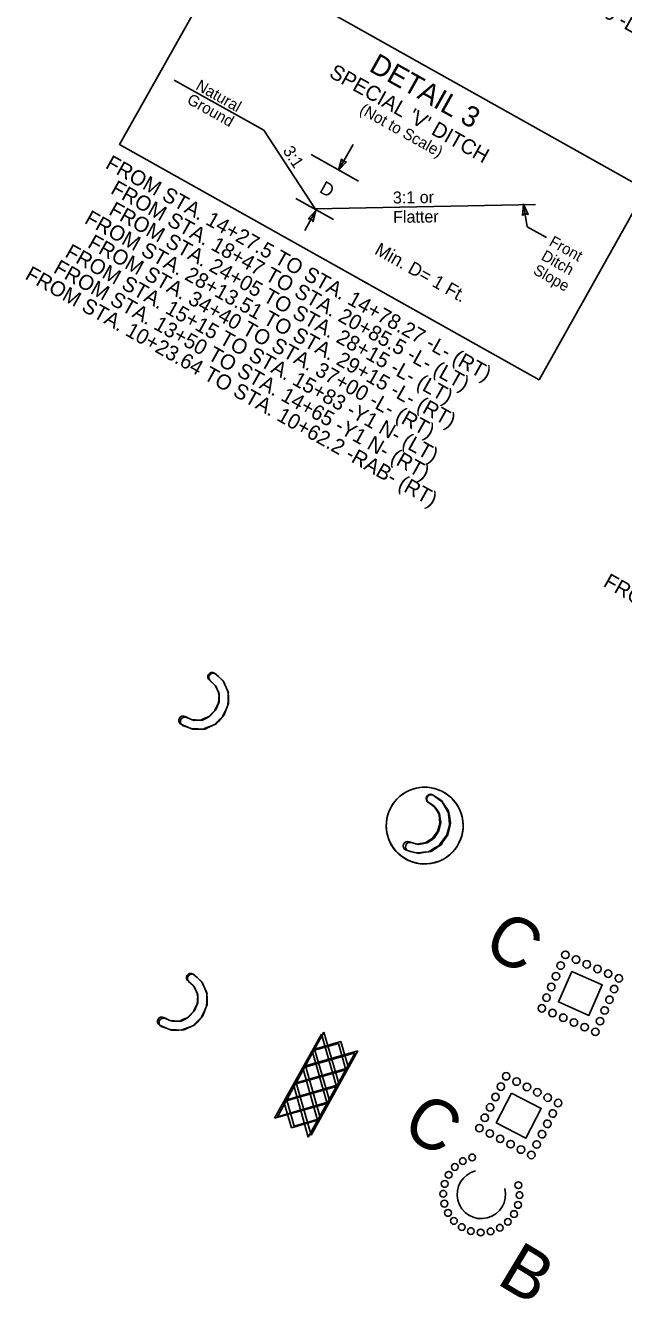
# Model space of a CAD drawing. Extents: x 2283629 to 2286552, y 529718 to 531440.
# Drawn here: x 2284114 to 2284293.2, y 530694.7 to 531076.3 of the extents above; entities that cross this region are included whole.
import ezdxf

# ---------------------------------------------------------------- set-up
doc = ezdxf.new("R2010")
doc.units = 0
for name, color, linetype in [('Draft_Corridor_Graphics_Final', 7, 'Continuous'), ('Draft_RDY_Construction_Class_Element', 7, 'Continuous'), ('P_NCDOT_Terrain_Breakline', 7, 'Continuous'), ('P_NCDOT_Terrain_Hole', 7, 'Continuous'), ('P_NCDOT_Terrain_Island', 7, 'Continuous'), ('P_NCDOT_Terrain_Model_Contour_Major', 7, 'Continuous'), ('P_NCDOT_Terrain_Model_Contour_Minor', 7, 'Continuous'), ('P_NCDOT_Terrain_Model_Triangles', 7, 'Continuous'), ('P_NCDOT_Terrain_Void', 7, 'Continuous'), ('P_RDY_TC_Pvmt_Asphalt_Intermediate_Course', 7, 'Continuous'), ('P_RDY_TC_Pvmt_Asphalt_Surface_Course', 7, 'Continuous'), ('P_RDY_TL_Sidewalk', 7, 'Continuous'), ('P_RDY_XS_Guardrail_Warrant_Red_Flag', 7, 'Continuous')]:
    doc.layers.add(name, color=color, linetype=linetype)

msp = doc.modelspace()

# ---------------------------------------------------------------- linework, layer by layer
at = {"layer": 'Draft_Corridor_Graphics_Final'}
for p, q in [((2284170.65, 530878.85), (2284170.9, 530878.63)), ((2284169.3, 530869.39), (2284168.24, 530868.85)), ((2284171.05, 530871.36), (2284171.05, 530871.35)), ((2284167.24, 530868.36), (2284167.03, 530868.25)), ((2284164.27, 530788.68), (2284164.51, 530788.46)), ((2284164.66, 530781.19), (2284164.66, 530781.18)), ((2284160.85, 530778.19), (2284160.64, 530778.08)), ((2284162.91, 530779.22), (2284161.85, 530778.68))]:
    msp.add_line(p, q, dxfattribs=at)
for points in [[(2284161.08, 530866.65), (2284162.53, 530866.11), (2284164.18, 530865.49), (2284164.99, 530865.51), (2284166.33, 530865.54), (2284167.84, 530865.57), (2284167.85, 530865.57), (2284168.18, 530865.73), (2284168.34, 530865.8), (2284169, 530866.1), (2284169.87, 530866.51), (2284170.08, 530866.61), (2284171.11, 530867.09), (2284171.8, 530867.85), (2284173.58, 530869.8), (2284173.59, 530869.81), (2284174.49, 530872.19), (2284174.86, 530873.17), (2284174.82, 530874.63), (2284174.8, 530875.3), (2284174.77, 530876.25), (2284174.77, 530876.33), (2284174.76, 530876.77), (2284174.76, 530876.81), (2284173.97, 530878.42), (2284173.53, 530879.33), (2284173.17, 530880.09), (2284171.81, 530881.29), (2284170.64, 530882.32)], [(2284169.28, 530880.11), (2284170.65, 530878.85), (2284170.9, 530878.63), (2284171.54, 530877.3), (2284171.99, 530876.37), (2284172, 530874.92), (2284172, 530873.72), (2284171.05, 530871.36), (2284171.05, 530871.35), (2284169.3, 530869.39), (2284168.24, 530868.85), (2284167.24, 530868.36), (2284167.03, 530868.25), (2284165.58, 530868.2), (2284164.48, 530868.16), (2284163.74, 530868.45), (2284162.3, 530869.02), (2284162.29, 530869.02)], [(2284154.69, 530776.48), (2284156.14, 530775.94), (2284157.79, 530775.32), (2284158.6, 530775.34), (2284159.94, 530775.37), (2284161.45, 530775.4), (2284161.46, 530775.4), (2284161.79, 530775.56), (2284161.95, 530775.63), (2284162.61, 530775.94), (2284163.48, 530776.34), (2284163.7, 530776.44), (2284164.72, 530776.92), (2284165.42, 530777.68), (2284167.19, 530779.63), (2284167.2, 530779.64), (2284168.1, 530782.02), (2284168.47, 530783), (2284168.43, 530784.46), (2284168.41, 530785.13), (2284168.39, 530786.08), (2284168.38, 530786.16), (2284168.37, 530786.6), (2284168.37, 530786.64), (2284167.58, 530788.25), (2284167.14, 530789.16), (2284166.78, 530789.92), (2284165.42, 530791.12), (2284164.25, 530792.15)], [(2284162.89, 530789.94), (2284164.27, 530788.68), (2284164.51, 530788.46), (2284165.15, 530787.13), (2284165.6, 530786.2), (2284165.61, 530784.75), (2284165.61, 530783.55), (2284164.66, 530781.19), (2284164.66, 530781.18), (2284162.91, 530779.22), (2284161.85, 530778.68), (2284160.85, 530778.19), (2284160.64, 530778.08), (2284159.19, 530778.03), (2284158.09, 530778), (2284157.35, 530778.28), (2284155.91, 530778.85), (2284155.9, 530778.85)]]:
    msp.add_lwpolyline(points, dxfattribs=at)
for centre, radius, start in [((2284169.96, 530881.21), 1.3, 58.4647), ((2284161.78, 530867.79), 1.33, 67.3521), ((2284163.57, 530791.04), 1.3, 58.4647), ((2284155.39, 530777.62), 1.33, 67.3521)]:
    msp.add_arc(centre, radius, start, 238.4647, dxfattribs=at)
at = {"layer": 'P_NCDOT_Terrain_Breakline'}
for p, q in [((2284207.84, 531033.02), (2284212.15, 531040.69)), ((2284199.58, 531037.65), (2284213.8, 531029.67)), ((2284195.01, 531024.54), (2284206.33, 531018.19)), ((2284263.18, 531022.84), (2284264.35, 531016.05)), ((2284201.05, 531020.91), (2284197.71, 531014.96)), ((2284270.15, 531012.79), (2284264.35, 531016.05))]:
    msp.add_line(p, q, dxfattribs=at)
for points in [[(2284174.2, 531097.74), (2284299.87, 531027.2), (2284267.86, 530970.18), (2284142.19, 531040.72), (2284174.2, 531097.74)], [(2284158.54, 531059.99), (2284185.38, 531045.02), (2284200.78, 531021.41), (2284266.77, 531022.73)]]:
    msp.add_lwpolyline(points, dxfattribs=at)
for points in [[(2284210.18, 531035.5), (2284207.84, 531033.02), (2284208.74, 531036.33), (2284209.27, 531035.55)], [(2284262.93, 531019.44), (2284263.18, 531022.84), (2284264.58, 531019.7), (2284263.67, 531019.98)], [(2284198.71, 531018.42), (2284201.05, 531020.91), (2284200.16, 531017.59), (2284199.63, 531018.38)]]:
    msp.add_lwpolyline(points, close=True, dxfattribs=at)
at = {"layer": 'P_NCDOT_Terrain_Model_Contour_Major'}
for p, q in [((2284236.42, 530842.46), (2284234.88, 530843.51)), ((2284236.41, 530842.45), (2284234.88, 530843.5)), ((2284236.41, 530842.45), (2284236.69, 530842.27)), ((2284236.42, 530842.46), (2284236.69, 530842.28)), ((2284237.52, 530841.05), (2284236.69, 530842.28)), ((2284237.51, 530841.04), (2284236.69, 530842.27)), ((2284238.08, 530840.18), (2284237.51, 530841.04)), ((2284238.09, 530840.19), (2284237.52, 530841.05)), ((2284238.29, 530838.75), (2284238.08, 530840.18)), ((2284238.3, 530838.76), (2284238.09, 530840.19)), ((2284238.47, 530837.56), (2284238.29, 530838.75)), ((2284238.47, 530837.57), (2284238.3, 530838.76)), ((2284236.4, 530832.89), (2284237.86, 530835.08)), ((2284236.41, 530832.9), (2284237.86, 530835.09)), ((2284237.86, 530835.1), (2284238.47, 530837.57)), ((2284237.86, 530835.09), (2284238.47, 530837.56)), ((2284237.86, 530835.1), (2284237.86, 530835.09)), ((2284237.86, 530835.09), (2284237.86, 530835.08)), ((2284229.52, 530831.55), (2284231.03, 530831.19)), ((2284229.52, 530831.54), (2284231.03, 530831.18)), ((2284231.03, 530831.19), (2284231.8, 530831.01)), ((2284231.03, 530831.18), (2284231.8, 530831)), ((2284231.8, 530831.01), (2284232.89, 530831.21)), ((2284231.8, 530831), (2284232.88, 530831.2)), ((2284232.88, 530831.2), (2284234.31, 530831.45)), ((2284232.89, 530831.21), (2284234.32, 530831.46)), ((2284234.51, 530831.58), (2284234.31, 530831.45)), ((2284234.51, 530831.59), (2284234.32, 530831.46)), ((2284234.51, 530831.59), (2284235.43, 530832.22)), ((2284234.51, 530831.58), (2284235.42, 530832.21)), ((2284236.4, 530832.89), (2284235.42, 530832.21)), ((2284236.41, 530832.9), (2284235.43, 530832.22))]:
    msp.add_line(p, q, dxfattribs=at)
for points in [[(2284235.91, 530845.89), (2284237.22, 530845.04), (2284238.73, 530844.04), (2284239.2, 530843.34), (2284239.76, 530842.5), (2284240.77, 530841.02), (2284240.77, 530840.98), (2284240.85, 530840.54), (2284240.86, 530840.47), (2284241.02, 530839.52), (2284241.13, 530838.87), (2284241.38, 530837.42), (2284241.15, 530836.41), (2284240.59, 530833.92), (2284240.59, 530833.91), (2284239.1, 530831.73), (2284238.52, 530830.88), (2284237.57, 530830.26), (2284237.37, 530830.13), (2284236.57, 530829.61), (2284235.95, 530829.21), (2284235.81, 530829.12), (2284235.5, 530828.92), (2284235.49, 530828.92), (2284234, 530828.67), (2284232.68, 530828.45), (2284231.88, 530828.32), (2284230.16, 530828.7), (2284228.65, 530829.04)], [(2284235.91, 530845.88), (2284237.21, 530845.03), (2284238.73, 530844.03), (2284239.2, 530843.33), (2284239.76, 530842.49), (2284240.76, 530841.01), (2284240.77, 530840.97), (2284240.84, 530840.53), (2284240.86, 530840.46), (2284241.02, 530839.51), (2284241.13, 530838.86), (2284241.38, 530837.41), (2284241.15, 530836.4), (2284240.59, 530833.91), (2284240.58, 530833.9), (2284239.1, 530831.72), (2284238.52, 530830.87), (2284237.57, 530830.25), (2284237.37, 530830.12), (2284236.56, 530829.6), (2284235.95, 530829.2), (2284235.8, 530829.11), (2284235.5, 530828.91), (2284235.49, 530828.91), (2284234, 530828.66), (2284232.67, 530828.44), (2284231.87, 530828.31), (2284230.16, 530828.69), (2284228.65, 530829.03)]]:
    msp.add_lwpolyline(points, dxfattribs=at)
for centre, radius, start, end in [((2284233.6, 530836.63), 11.5, 66.5279, 238.9333), ((2284233.64, 530836.61), 11.5, 246.5279, 59.1744), ((2284235.39, 530844.69), 1.3, 66.5279, 246.5279), ((2284235.4, 530844.7), 1.3, 66.5279, 246.5279), ((2284233.6, 530836.63), 11.5, 58.9333, 66.5279), ((2284229.18, 530830.25), 1.33, 75.4153, 246.5279), ((2284229.18, 530830.26), 1.33, 75.4153, 246.5279), ((2284233.64, 530836.61), 11.5, 238.6921, 246.5279)]:
    msp.add_arc(centre, radius, start, end, dxfattribs=at)
at = {"layer": 'P_NCDOT_Terrain_Model_Contour_Minor'}
for p, q in [((2284236.43, 530842.29), (2284234.95, 530843.43)), ((2284236.43, 530842.29), (2284234.95, 530843.43)), ((2284236.43, 530842.29), (2284236.69, 530842.09)), ((2284236.43, 530842.29), (2284236.69, 530842.09)), ((2284237.44, 530840.82), (2284236.69, 530842.09)), ((2284237.44, 530840.82), (2284236.69, 530842.09)), ((2284237.96, 530839.93), (2284237.44, 530840.82)), ((2284237.96, 530839.93), (2284237.44, 530840.82)), ((2284238.09, 530838.49), (2284237.96, 530839.93)), ((2284238.09, 530838.49), (2284237.96, 530839.93)), ((2284238.2, 530837.29), (2284238.09, 530838.49)), ((2284238.2, 530837.29), (2284238.09, 530838.49)), ((2284235.87, 530832.75), (2284237.45, 530834.85)), ((2284235.87, 530832.75), (2284237.45, 530834.85)), ((2284237.45, 530834.86), (2284238.2, 530837.29)), ((2284237.45, 530834.86), (2284238.2, 530837.29)), ((2284237.45, 530834.86), (2284237.45, 530834.85)), ((2284237.45, 530834.86), (2284237.45, 530834.85)), ((2284228.92, 530831.79), (2284230.41, 530831.35)), ((2284228.92, 530831.79), (2284230.41, 530831.35)), ((2284230.41, 530831.35), (2284231.17, 530831.12)), ((2284230.41, 530831.35), (2284231.17, 530831.12)), ((2284231.17, 530831.12), (2284232.26, 530831.25)), ((2284231.17, 530831.12), (2284232.26, 530831.25)), ((2284232.26, 530831.25), (2284233.7, 530831.43)), ((2284232.26, 530831.25), (2284233.7, 530831.43)), ((2284233.91, 530831.55), (2284233.7, 530831.43)), ((2284233.91, 530831.55), (2284233.7, 530831.43)), ((2284233.91, 530831.55), (2284234.85, 530832.12)), ((2284233.91, 530831.55), (2284234.85, 530832.12)), ((2284235.87, 530832.75), (2284234.85, 530832.12)), ((2284235.87, 530832.75), (2284234.85, 530832.12))]:
    msp.add_line(p, q, dxfattribs=at)
msp.add_lwpolyline([(2284236.12, 530845.75), (2284237.37, 530844.82), (2284238.83, 530843.73), (2284239.25, 530843.01), (2284239.77, 530842.14), (2284240.69, 530840.6), (2284240.69, 530840.56), (2284240.74, 530840.12), (2284240.75, 530840.05), (2284240.86, 530839.1), (2284240.93, 530838.44), (2284241.09, 530836.98), (2284240.81, 530835.98), (2284240.11, 530833.53), (2284240.1, 530833.52), (2284238.49, 530831.42), (2284237.87, 530830.61), (2284236.88, 530830.05), (2284236.68, 530829.93), (2284235.84, 530829.45), (2284235.21, 530829.09), (2284235.06, 530829.01), (2284234.74, 530828.82), (2284234.73, 530828.82), (2284233.23, 530828.66), (2284231.9, 530828.52), (2284231.09, 530828.43), (2284229.4, 530828.91), (2284227.91, 530829.33)], dxfattribs=at)
msp.add_lwpolyline([(2284236.12, 530845.75), (2284237.37, 530844.82), (2284238.83, 530843.73), (2284239.25, 530843.01), (2284239.77, 530842.14), (2284240.69, 530840.6), (2284240.69, 530840.56), (2284240.74, 530840.12), (2284240.75, 530840.05), (2284240.86, 530839.1), (2284240.93, 530838.44), (2284241.09, 530836.98), (2284240.81, 530835.98), (2284240.11, 530833.53), (2284240.1, 530833.52), (2284238.49, 530831.42), (2284237.87, 530830.61), (2284236.88, 530830.05), (2284236.68, 530829.93), (2284235.84, 530829.45), (2284235.21, 530829.09), (2284235.06, 530829.01), (2284234.74, 530828.82), (2284234.73, 530828.82), (2284233.23, 530828.66), (2284231.9, 530828.52), (2284231.09, 530828.43), (2284229.4, 530828.91), (2284227.91, 530829.33)], dxfattribs=at)
for centre, radius, start, end in [((2284233.62, 530836.65), 11.5, 63.2706, 153.2706), ((2284235.53, 530844.59), 1.3, 63.2706, 243.2706), ((2284235.53, 530844.59), 1.3, 63.2706, 243.2706), ((2284233.62, 530836.65), 11.5, 333.2706, 63.2706), ((2284233.62, 530836.65), 11.5, 153.2706, 243.2706), ((2284228.51, 530830.52), 1.33, 72.158, 243.2706), ((2284228.51, 530830.52), 1.33, 72.158, 243.2706), ((2284233.62, 530836.65), 11.5, 243.2706, 333.2706)]:
    msp.add_arc(centre, radius, start, end, dxfattribs=at)
at = {"layer": 'P_NCDOT_Terrain_Model_Triangles'}
for p, q in [((2284170.83, 530878.62), (2284171.06, 530878.38)), ((2284168.89, 530869.25), (2284167.79, 530868.78)), ((2284170.76, 530871.11), (2284170.75, 530871.1)), ((2284166.77, 530868.35), (2284166.55, 530868.26)), ((2284164.44, 530788.45), (2284164.67, 530788.21)), ((2284164.37, 530780.94), (2284164.37, 530780.94)), ((2284160.38, 530778.18), (2284160.16, 530778.09)), ((2284162.5, 530779.08), (2284161.4, 530778.61))]:
    msp.add_line(p, q, dxfattribs=at)
for points in [[(2284160.52, 530867.03), (2284161.93, 530866.4), (2284163.53, 530865.68), (2284164.34, 530865.65), (2284165.68, 530865.59), (2284167.19, 530865.53), (2284167.2, 530865.53), (2284167.54, 530865.67), (2284167.7, 530865.73), (2284168.38, 530865.99), (2284169.28, 530866.34), (2284169.5, 530866.43), (2284170.55, 530866.84), (2284171.29, 530867.56), (2284173.19, 530869.4), (2284173.19, 530869.41), (2284174.25, 530871.73), (2284174.67, 530872.68), (2284174.72, 530874.14), (2284174.75, 530874.81), (2284174.78, 530875.76), (2284174.78, 530875.84), (2284174.79, 530876.28), (2284174.8, 530876.32), (2284174.11, 530877.98), (2284173.73, 530878.92), (2284173.41, 530879.69), (2284172.13, 530880.97), (2284171.02, 530882.08)], [(2284169.53, 530879.95), (2284170.83, 530878.62), (2284171.06, 530878.38), (2284171.62, 530877.01), (2284172, 530876.05), (2284171.92, 530874.61), (2284171.85, 530873.41), (2284170.76, 530871.11), (2284170.75, 530871.1), (2284168.89, 530869.25), (2284167.79, 530868.78), (2284166.77, 530868.35), (2284166.55, 530868.26), (2284165.1, 530868.3), (2284164, 530868.33), (2284163.28, 530868.66), (2284161.87, 530869.32), (2284161.87, 530869.32)], [(2284154.13, 530776.86), (2284155.54, 530776.23), (2284157.14, 530775.51), (2284157.95, 530775.48), (2284159.29, 530775.42), (2284160.8, 530775.36), (2284160.81, 530775.36), (2284161.15, 530775.5), (2284161.31, 530775.56), (2284161.99, 530775.82), (2284162.89, 530776.17), (2284163.11, 530776.26), (2284164.16, 530776.67), (2284164.9, 530777.39), (2284166.8, 530779.23), (2284166.8, 530779.24), (2284167.86, 530781.56), (2284168.28, 530782.51), (2284168.33, 530783.97), (2284168.36, 530784.64), (2284168.39, 530785.59), (2284168.39, 530785.67), (2284168.4, 530786.11), (2284168.41, 530786.15), (2284167.72, 530787.81), (2284167.34, 530788.75), (2284167.02, 530789.52), (2284165.74, 530790.8), (2284164.64, 530791.91)], [(2284163.14, 530789.78), (2284164.44, 530788.45), (2284164.67, 530788.21), (2284165.23, 530786.84), (2284165.61, 530785.88), (2284165.53, 530784.44), (2284165.46, 530783.24), (2284164.37, 530780.94), (2284164.37, 530780.94), (2284162.5, 530779.08), (2284161.4, 530778.61), (2284160.38, 530778.18), (2284160.16, 530778.09), (2284158.71, 530778.13), (2284157.61, 530778.16), (2284156.89, 530778.49), (2284155.48, 530779.15), (2284155.48, 530779.15)]]:
    msp.add_lwpolyline(points, dxfattribs=at)
for centre, radius, start in [((2284170.28, 530881.01), 1.3, 54.9053), ((2284161.28, 530868.12), 1.33, 63.7927), ((2284163.89, 530790.84), 1.3, 54.9053), ((2284154.89, 530777.95), 1.33, 63.7927)]:
    msp.add_arc(centre, radius, start, 234.9053, dxfattribs=at)
at = {"layer": 'P_NCDOT_Terrain_Void'}
for p, q in [((2284188.65, 530748.95), (2284202.72, 530774.19)), ((2284202.72, 530774.19), (2284207.19, 530758.48)), ((2284207.75, 530771.4), (2284199.89, 530769.13)), ((2284207.75, 530771.4), (2284209.99, 530763.5)), ((2284212.81, 530768.56), (2284197.1, 530764.1)), ((2284198.74, 530743.32), (2284212.81, 530768.56)), ((2284199.89, 530769.13), (2284204.36, 530753.41)), ((2284209.99, 530763.5), (2284194.27, 530759.03)), ((2284197.1, 530764.1), (2284201.54, 530748.34)), ((2284207.19, 530758.48), (2284191.45, 530753.97)), ((2284194.27, 530759.03), (2284198.74, 530743.32)), ((2284204.36, 530753.41), (2284188.65, 530748.95)), ((2284191.47, 530753.9), (2284193.67, 530746.13)), ((2284201.54, 530748.34), (2284193.67, 530746.13))]:
    msp.add_line(p, q, dxfattribs=at)
at = {"layer": 'P_RDY_TC_Pvmt_Asphalt_Intermediate_Course'}
for p, q in [((2284292.78, 530790.36), (2284292.82, 530790.46)), ((2284291.37, 530787.16), (2284291.41, 530787.25)), ((2284288.56, 530780.76), (2284288.59, 530780.83)), ((2284289.97, 530783.96), (2284290, 530784.04)), ((2284274.55, 530752.96), (2284274.6, 530753.06)), ((2284271.35, 530746.75), (2284271.39, 530746.82)), ((2284272.95, 530749.85), (2284273, 530749.94)), ((2284269.75, 530743.64), (2284269.78, 530743.71))]:
    msp.add_line(p, q, dxfattribs=at)
for points in [[(2284277.68, 530792.94), (2284286.83, 530788.92), (2284282.81, 530779.76), (2284273.66, 530783.8)], [(2284259.64, 530756.47), (2284268.53, 530751.89), (2284263.94, 530743), (2284255.06, 530747.59)]]:
    msp.add_lwpolyline(points, close=True, dxfattribs=at)
for centre in [(2284275.76, 530797.91), (2284278.96, 530796.5), (2284282.17, 530795.09), (2284272.94, 530791.5), (2284274.35, 530794.7), (2284285.37, 530793.68), (2284288.57, 530792.27), (2284271.53, 530788.29), (2284270.12, 530785.09), (2284268.71, 530781.89), (2284271.91, 530780.48), (2284275.12, 530779.07), (2284278.32, 530777.66), (2284281.52, 530776.25), (2284286.14, 530778.04), (2284284.73, 530774.84), (2284258.03, 530761.54), (2284256.42, 530758.43), (2284261.14, 530759.94), (2284264.25, 530758.33), (2284267.36, 530756.73), (2284254.82, 530755.32), (2284270.47, 530755.13), (2284251.61, 530749.1), (2284253.21, 530752.21), (2284250.01, 530745.99), (2284253.12, 530744.39), (2284256.23, 530742.78), (2284259.34, 530741.18), (2284262.45, 530739.57), (2284265.56, 530737.97), (2284267.16, 530741.08)]:
    msp.add_circle(centre, 1.12, dxfattribs=at)
for centre, start, end in [((2284290.37, 530787.65), 338.7676, 333.7447), ((2284291.78, 530790.86), 339.0641, 333.4482), ((2284288.96, 530784.45), 338.4311, 334.0812), ((2284287.55, 530781.25), 338.0319, 334.4803), ((2284273.58, 530753.52), 335.5291, 329.9132), ((2284271.98, 530750.41), 335.2326, 330.2097), ((2284270.37, 530747.3), 334.8961, 330.5462), ((2284268.77, 530744.19), 334.4969, 330.9453)]:
    msp.add_arc(centre, 1.12, start, end, dxfattribs=at)
at = {"layer": 'P_RDY_TL_Sidewalk'}
for p, q in [((2284189.53, 530749.41), (2284203.43, 530774.74)), ((2284203.43, 530774.74), (2284208, 530759.06)), ((2284213.56, 530769.18), (2284197.88, 530764.62)), ((2284199.65, 530743.85), (2284213.56, 530769.18)), ((2284208.48, 530771.99), (2284200.63, 530769.66)), ((2284200.63, 530769.66), (2284205.21, 530753.97)), ((2284208.48, 530771.99), (2284210.77, 530764.1)), ((2284210.77, 530764.1), (2284195.09, 530759.53)), ((2284197.88, 530764.62), (2284202.42, 530748.89)), ((2284208, 530759.06), (2284192.3, 530754.45)), ((2284195.09, 530759.53), (2284199.65, 530743.85)), ((2284205.21, 530753.97), (2284189.53, 530749.41)), ((2284192.32, 530754.38), (2284194.56, 530746.63)), ((2284202.42, 530748.89), (2284194.56, 530746.63))]:
    msp.add_line(p, q, dxfattribs=at)
at = {"layer": 'P_RDY_XS_Guardrail_Warrant_Red_Flag'}
for centre in [(2284242.65, 530734.36), (2284245.05, 530736.13), (2284247.83, 530737.22), (2284240.8, 530732.02), (2284239.17, 530726.34), (2284239.61, 530729.29), (2284261.67, 530728.9), (2284239.51, 530723.38), (2284261.57, 530722.99), (2284262.01, 530725.94), (2284240.6, 530720.6), (2284260.38, 530720.26), (2284242.37, 530718.2), (2284244.71, 530716.35), (2284247.44, 530715.16), (2284253.35, 530715.06), (2284256.13, 530716.15), (2284258.53, 530717.92), (2284250.39, 530714.72)]:
    msp.add_circle(centre, 1.01, dxfattribs=at)
msp.add_arc((2284250.59, 530726.14), 7.26, 104.0082, 13.9994, dxfattribs=at)

# ---------------------------------------------------------------- texts
at = {"layer": 'Draft_RDY_Construction_Class_Element'}
msp.add_text('B', height=15, rotation=329.0088, dxfattribs=at).set_placement((2284254.79, 530699.61))
at = {"layer": 'P_NCDOT_Terrain_Breakline'}
for s, height, rotation, p in [('DETAIL 3', 6.187, 330.6931, (2284216.62, 531062.85)), ("SPECIAL 'V' DITCH", 4.4997, 330.6931, (2284204.68, 531061.09)), ('Natural', 3.375, 330.6931, (2284164.77, 531057.36)), ('Ground', 3.375, 330.6931, (2284162.12, 531053.17)), ('(Not to Scale)', 3.375, 330.6931, (2284213.81, 531050.21)), ('3:1', 3.6, 302.9443, (2284190.99, 531038.83)), ('FROM STA. 14+27.5 TO STA. 14+78.27 -L- (RT)', 4.5, 330.6931, (2284137.67, 531033.8)), ('FROM STA. 18+47 TO STA. 20+85.5 -L- (LT)', 4.5, 330.6931, (2284139.24, 531026.24)), ('D', 3.94, 330.6931, (2284201.78, 531026.51)), ('3:1 or', 3.6, 0.6931, (2284224.11, 531023)), ('FROM STA. 24+05 TO STA. 28+15 -L- (LT)', 4.5, 330.6931, (2284138.67, 531019.88)), ('FROM STA. 28+13.51 TO STA. 29+15 -L- (RT)', 4.5, 330.6931, (2284131.4, 531017.28)), ('Flatter', 3.6, 0.6931, (2284224.18, 531017.18)), ('FROM STA. 34+40 TO STA. 37+00 -L- (RT)', 4.5, 330.6931, (2284132.36, 531010.06)), ('FROM STA. 15+15 TO STA. 15+83 -Y1 N- (LT)', 4.5, 330.6931, (2284125.55, 531007.21)), ('Min. D= 1 Ft.', 3.9374, 330.6931, (2284218.31, 531008.06)), ('Front', 3.33, 330.6931, (2284270.63, 531010.61)), ('FROM STA. 13+50 TO STA. 14+65 -Y1 N- (RT)', 4.5, 330.6931, (2284122.09, 531002.47)), ('Ditch', 3.33, 330.6931, (2284268.24, 531006.35)), ('FROM STA. 10+23.64 TO STA. 10+62.2 -RAB- (RT)', 4.5, 330.6931, (2284113.6, 531000.56)), ('Slope', 3.33, 330.6931, (2284265.85, 531002.09))]:
    msp.add_text(s, height=height, rotation=rotation, dxfattribs=at).set_placement(p)
at = {"layer": 'P_NCDOT_Terrain_Hole'}
msp.add_text('FROM STA. 27+51.5 TO STA. 28+10 -L- (RT)', height=4.5, rotation=330.6931, dxfattribs=at).set_placement((2284202.59, 531126.34))
at = {"layer": 'P_NCDOT_Terrain_Island'}
msp.add_text('FROM STA. 12+41.46 TO STA. 12+84.45 -RAB- (RT)', height=4.5, rotation=330.6931, dxfattribs=at).set_placement((2284286.82, 530908.49))
at = {"layer": 'P_RDY_TC_Pvmt_Asphalt_Surface_Course'}
for p in [(2284250.43, 530799.09), (2284226.12, 530744.55)]:
    msp.add_text('C', height=15, rotation=329.1861, dxfattribs=at).set_placement(p)

doc.saveas('drawing.dxf')
